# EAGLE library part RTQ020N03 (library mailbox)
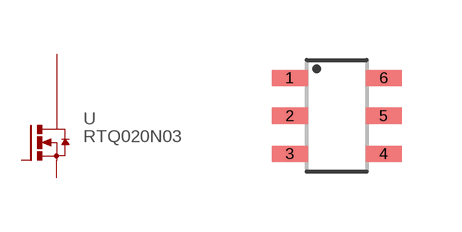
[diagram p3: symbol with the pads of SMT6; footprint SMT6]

Designator prefix -

## RTQ020N03  [SMT6]
1  D  pas
2  D1  pas
3  G  pas
4  S  pas
5  D2  pas
6  D3  pas

## Footprint SMT6 (pad centres in mm)
SMT6 Package EIAJ : SC-74 Source: http://www.rohm.com/products/databook/tr/pdf/umx1n.pdf
smd 0.9 x 0.4: 1 -1.175,0.95; 2 -1.175,0; 3 -1.175,-0.95; 4 1.175,-0.95; 5 1.175,0; 6 1.175,0.95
